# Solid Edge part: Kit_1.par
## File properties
Author: bmolnar
Last saved by: bmolnar
Revision: 77
Sűrűség: 0,000 kg/m^3
Pontosság: 0,990
Username: bmolnar
Dokumentum tartalom típus: 0
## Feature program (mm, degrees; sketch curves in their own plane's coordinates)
base feature "unnamed BaseFeature 1"
sketch for "unnamed Hole 1" plane through (-23.25, -23.25, 5) normal (0, 0, -1) x-axis (0, -1, 0)
  hole centre (0, 0) bore radius 3.3235
hole "unnamed Hole 1" through
sketch for "unnamed Hole 2" plane through (-23.25, -23.25, 5) normal (0, 0, -1) x-axis (0, -1, 0)
  hole centre (-46.5, 0) bore radius 3.3235
hole "unnamed Hole 2" through
sketch for "unnamed Hole 3" plane through (-23.25, -23.25, 5) normal (0, 0, -1) x-axis (0, -1, 0)
  hole centre (-46.5, -46.5) bore radius 3.3235
hole "unnamed Hole 3" through
sketch for "unnamed Hole 4" plane through (-23.25, -23.25, 5) normal (0, 0, -1) x-axis (0, -1, 0)
  hole centre (0, -46.5) bore radius 3.3235
hole "unnamed Hole 4" through
pattern "unnamed Pattern 1" of "unnamed Hole 1", "unnamed Hole 2", "unnamed Hole 3", "unnamed Hole 4"
sketch for "Furat_5" plane through (-32.75, 0, -18.2488) normal (1, 0, 0) x-axis (0, 1, 0)
  hole centre (0, 26.2488) bore radius 4.283
hole "Furat_5" nominal diameter 9.728 finite  ThreadDepth = 10 mm
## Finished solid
Body 1: solid body, 302 faces, 729 edges, 446 vertices, 4 internal voids.
  Faces by surface: plane 139, cylinder 78, swept 53, torus 20, cone 11, spline 1
  Edges by curve: line 413, circle 160, spline 118, ellipse 28, curve on surface 10
Bounding box of the edges (mm; curved faces can reach further): 65.500 x 65.500 x 14.500, from (-32.75, -32.75, 0) to (32.75, 32.75, 14.5).
Cylindrical faces by radius (mm): R0.2 x40, R0.201 x2, R0.2012 x2, R2.5402 x12, R2.6 x4, R3.3235 x4, R3.75 x4, R3.85 x4, R4.283 x1, R5.25 x4, R6 x1
Conical faces (half-angle, radius in mm at the cone's reference point): 0.5 deg R6.5 x2, 0.5 deg R8 x4, 45 deg R3.6735 x4, 45 deg R6.15 x1
Toroidal faces (ring radius, tube radius in mm): R2.9402 r0.4 x12, R3.55 r0.2 x8
Planar faces by outward normal: +x 11, +y 12, +z 1, -x 13, -y 12, -z 22, oblique 68
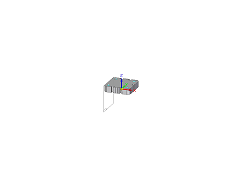
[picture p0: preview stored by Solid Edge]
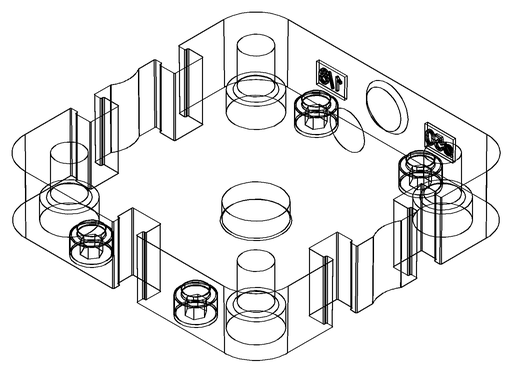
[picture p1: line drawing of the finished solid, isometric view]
